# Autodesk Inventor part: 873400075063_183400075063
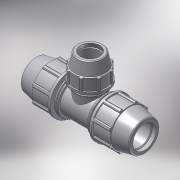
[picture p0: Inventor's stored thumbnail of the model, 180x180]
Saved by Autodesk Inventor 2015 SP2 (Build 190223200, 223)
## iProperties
Created: 2017-02
Part Number: 873400075063_183400075063
Material: PVC-Piping
Description: PLASSON REDUCING TEE 75-63-75
Document SubType Name: Modeling
Designer: KIM
Mass: 92.6774 g
Surface Area: 199.44 cm^2
Volume: 66.1981 cm^3
Density: 1.4 g/cm^3
Appearance: Smooth - White
Author: KIM
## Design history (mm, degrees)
derived "87340.ipt"
feature "Solid1::87340.ipt"
feature "Solid2::87340.ipt"
tag "TaggingFeature1"
body "Solid1"
other parameters: "d2" = 75, "d4" = 15.16667, "d5" = 50.96, "d7" = 132, "d11" = 6.06667, "d13" = 120 deg, "d14" = 97.5, "d15" = 12 deg, "d16" = 114.84, "d18" = 3.75, "d19" = 35 deg, "d20" = 17.5 deg, "d21" = 122.76, "d23" = 0, "d25" = 360 deg, "d27" = 2.64, "d33" = 1.5, "d42" = 65.52, "d43" = 3.96, "d46" = 2.25, "d67" = 99, "d76" = 63, "d77" = 113, "d78" = 12 deg, "d79" = 153, "d80" = 120 deg, "d81" = 81.9, "d82" = 12.75, "d87" = 5.1, "d89" = 38.25, "d90" = 45.9, "d96" = 30.33333, "d98" = 105.09, "d99" = 35 deg, "d100" = 17.5 deg, "d102" = 0, "d103" = 2.26, "d107" = 360 deg, "d109" = 1.89, "d112" = 3.15, "d113" = 7.53333, "d114" = 0, "d117" = 364, "d118" = 98.31, "d126" = 67.5, "d127" = 137, "d131" = 7.65, "d132" = 56.7, "d133" = 109, "d135" = 0, "d138" = 10.92, "d143" = 0, "d148" = 84.75, "d168" = 67.5, "d170" = 0, "d171" = 63, "d173" = 0, "d176" = 7.53333, "d177" = 0, "d178" = 111.3948, "d179" = 3.64, "d180" = 3.64, "d181" = 2.55, "d182" = 95.3607, "d183" = 2.55, "d_" = 75, "E_" = 132, "A_" = 153, "l_" = 137, "E_1" = 113, "l_1" = 109, "d_1" = 63, "H_" = 364
